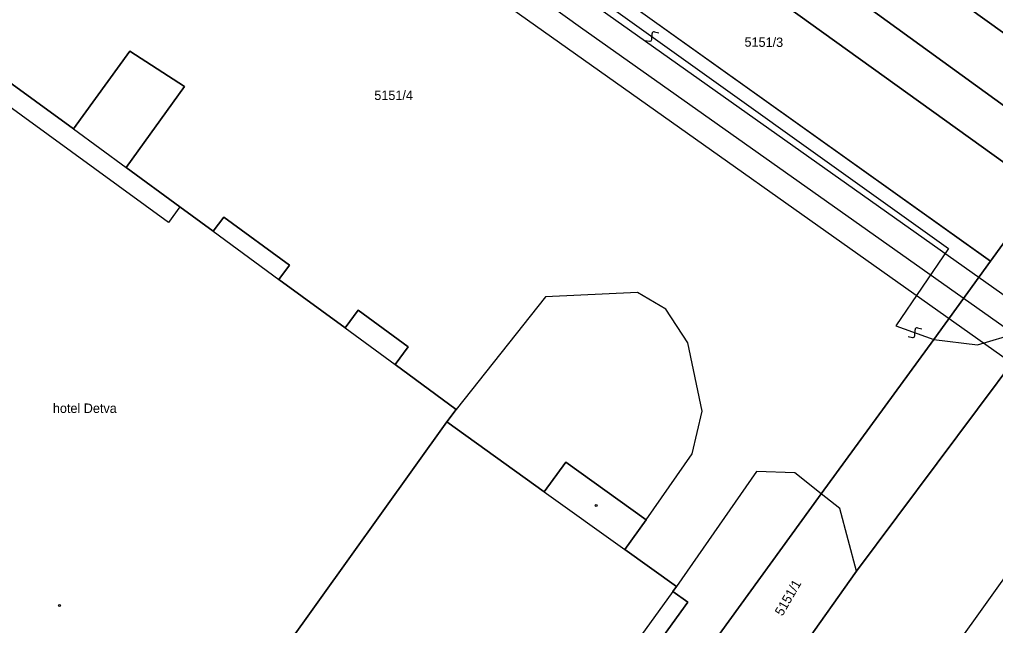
# Model space of a CAD drawing. Extents: x -400488 to -400124, y -1251493 to -1251223.
# Drawn here: x -400364.05 to -400314.45, y -1251437 to -1251406.21 of the extents above; entities that cross this region are included whole.
import ezdxf

# ---------------------------------------------------------------- set-up
doc = ezdxf.new("R2010")
doc.units = 0
doc.layers.add('Level 63', color=7, linetype='Continuous')

msp = doc.modelspace()

# ---------------------------------------------------------------- linework, layer by layer
at = {"layer": 'Level 63'}
for p, q in [((-400343.89, -1251392), (-400312.09, -1251414.87)), ((-400312.09, -1251414.87), (-400343.89, -1251392)), ((-400314.7, -1251418.49), (-400346.59, -1251395.74)), ((-400346.59, -1251395.74), (-400314.7, -1251418.49)), ((-400346.99, -1251396.3), (-400316.83, -1251417.85)), ((-400346.99, -1251396.3), (-400316.83, -1251417.85)), ((-400341.41, -1251400.8), (-400300.81, -1251429.57)), ((-400300.27, -1251433.14), (-400345.06, -1251401.4)), ((-400343.23, -1251401.1), (-400335.53, -1251406.59)), ((-400311.14, -1251408.98), (-400321.44, -1251401.55)), ((-400321.44, -1251401.55), (-400311.14, -1251408.98)), ((-400323.17, -1251403.95), (-400310.73, -1251412.98)), ((-400310.73, -1251412.98), (-400323.17, -1251403.95)), ((-400335.53, -1251406.59), (-400300.54, -1251431.36)), ((-400331.916, -1251407.222), (-400331.904, -1251406.928)), ((-400331.783, -1251406.834), (-400331.565, -1251406.882)), ((-400332.255, -1251407.268), (-400332.037, -1251407.316)), ((-400366.76, -1251407.8), (-400361.31, -1251411.77)), ((-400361.31, -1251411.77), (-400366.76, -1251407.8)), ((-400361.31, -1251411.77), (-400358.44, -1251407.82)), ((-400358.44, -1251407.82), (-400361.31, -1251411.77)), ((-400358.44, -1251407.82), (-400355.66, -1251409.61)), ((-400355.66, -1251409.61), (-400358.44, -1251407.82)), ((-400356.48, -1251416.53), (-400367.35, -1251408.62)), ((-400355.66, -1251409.61), (-400358.63, -1251413.73)), ((-400358.63, -1251413.73), (-400355.66, -1251409.61)), ((-400361.31, -1251411.77), (-400358.63, -1251413.73)), ((-400358.63, -1251413.73), (-400355.89, -1251415.73)), ((-400355.89, -1251415.73), (-400358.63, -1251413.73)), ((-400312.09, -1251414.87), (-400314.7, -1251418.49)), ((-400314.7, -1251418.49), (-400312.09, -1251414.87)), ((-400355.89, -1251415.73), (-400356.48, -1251416.53)), ((-400355.89, -1251415.73), (-400354.2, -1251416.97)), ((-400354.2, -1251416.97), (-400355.89, -1251415.73)), ((-400354.2, -1251416.97), (-400353.67, -1251416.25)), ((-400353.67, -1251416.25), (-400354.2, -1251416.97)), ((-400353.67, -1251416.25), (-400350.33, -1251418.69)), ((-400350.33, -1251418.69), (-400353.67, -1251416.25)), ((-400354.2, -1251416.97), (-400350.86, -1251419.42)), ((-400354.2, -1251416.97), (-400350.86, -1251419.42)), ((-400316.83, -1251417.85), (-400319.51, -1251421.77)), ((-400316.83, -1251417.85), (-400319.51, -1251421.77)), ((-400350.33, -1251418.69), (-400350.86, -1251419.42)), ((-400350.86, -1251419.42), (-400350.33, -1251418.69)), ((-400317.58, -1251422.47), (-400314.7, -1251418.49)), ((-400314.7, -1251418.49), (-400317.58, -1251422.47)), ((-400350.86, -1251419.42), (-400347.5, -1251421.88)), ((-400347.5, -1251421.88), (-400350.86, -1251419.42)), ((-400337.31, -1251420.3), (-400341.86, -1251426.02)), ((-400337.31, -1251420.3), (-400341.86, -1251426.02)), ((-400332.64, -1251420.08), (-400337.31, -1251420.3)), ((-400332.64, -1251420.08), (-400337.31, -1251420.3)), ((-400331.2, -1251420.92), (-400332.64, -1251420.08)), ((-400331.2, -1251420.92), (-400332.64, -1251420.08)), ((-400347.5, -1251421.88), (-400346.84, -1251420.98)), ((-400346.84, -1251420.98), (-400347.5, -1251421.88)), ((-400346.84, -1251420.98), (-400344.3, -1251422.84)), ((-400344.3, -1251422.84), (-400346.84, -1251420.98)), ((-400330.09, -1251422.64), (-400331.2, -1251420.92)), ((-400330.09, -1251422.64), (-400331.2, -1251420.92)), ((-400347.5, -1251421.88), (-400344.96, -1251423.74)), ((-400321.51, -1251434.24), (-400312.23, -1251421.8)), ((-400312.23, -1251421.8), (-400321.51, -1251434.24)), ((-400319.51, -1251421.77), (-400317.58, -1251422.47)), ((-400319.51, -1251421.77), (-400317.58, -1251422.47)), ((-400318.418, -1251421.879), (-400318.2, -1251421.927)), ((-400315.36, -1251422.74), (-400312.23, -1251421.8)), ((-400318.89, -1251422.313), (-400318.672, -1251422.361)), ((-400318.551, -1251422.267), (-400318.539, -1251421.973)), ((-400344.3, -1251422.84), (-400344.96, -1251423.74)), ((-400344.96, -1251423.74), (-400344.3, -1251422.84)), ((-400329.36, -1251426.11), (-400330.09, -1251422.64)), ((-400329.36, -1251426.11), (-400330.09, -1251422.64)), ((-400323.3, -1251430.31), (-400317.58, -1251422.47)), ((-400317.58, -1251422.47), (-400323.3, -1251430.31)), ((-400317.58, -1251422.47), (-400315.36, -1251422.74)), ((-400344.96, -1251423.74), (-400341.86, -1251426.02)), ((-400341.86, -1251426.02), (-400344.96, -1251423.74)), ((-400341.86, -1251426.02), (-400342.33, -1251426.66)), ((-400342.33, -1251426.66), (-400341.86, -1251426.02)), ((-400329.86, -1251428.28), (-400329.36, -1251426.11)), ((-400329.86, -1251428.28), (-400329.36, -1251426.11)), ((-400350.86, -1251438.57), (-400342.33, -1251426.66)), ((-400342.33, -1251426.66), (-400350.86, -1251438.57)), ((-400342.33, -1251426.66), (-400337.38, -1251430.21)), ((-400337.38, -1251430.21), (-400342.33, -1251426.66)), ((-400332.2, -1251431.63), (-400329.86, -1251428.28)), ((-400332.2, -1251431.63), (-400329.86, -1251428.28)), ((-400337.38, -1251430.21), (-400336.29, -1251428.7)), ((-400336.29, -1251428.7), (-400337.38, -1251430.21)), ((-400336.29, -1251428.7), (-400332.2, -1251431.63)), ((-400332.2, -1251431.63), (-400336.29, -1251428.7)), ((-400326.59, -1251429.17), (-400330.66, -1251435.02)), ((-400326.59, -1251429.17), (-400330.66, -1251435.02)), ((-400324.65, -1251429.24), (-400326.59, -1251429.17)), ((-400324.65, -1251429.24), (-400326.59, -1251429.17)), ((-400323.3, -1251430.31), (-400324.65, -1251429.24)), ((-400345.99, -1251461.49), (-400323.3, -1251430.31)), ((-400323.3, -1251430.31), (-400345.99, -1251461.49)), ((-400337.38, -1251430.21), (-400333.28, -1251433.14)), ((-400322.36, -1251431.06), (-400323.3, -1251430.31)), ((-400321.51, -1251434.24), (-400322.36, -1251431.06)), ((-400332.2, -1251431.63), (-400333.28, -1251433.14)), ((-400333.28, -1251433.14), (-400332.2, -1251431.63)), ((-400333.28, -1251433.14), (-400330.66, -1251435.02)), ((-400330.66, -1251435.02), (-400333.28, -1251433.14)), ((-400312.95, -1251433.09), (-400317.46, -1251439.39)), ((-400342.61, -1251463.85), (-400321.51, -1251434.24)), ((-400321.51, -1251434.24), (-400342.61, -1251463.85)), ((-400330.84, -1251435.27), (-400347.7, -1251458.61)), ((-400330.66, -1251435.02), (-400330.84, -1251435.27)), ((-400330.84, -1251435.27), (-400330.66, -1251435.02)), ((-400330.84, -1251435.27), (-400330.08, -1251435.81)), ((-400330.08, -1251435.81), (-400330.84, -1251435.27)), ((-400330.08, -1251435.81), (-400346.94, -1251459.15)), ((-400346.94, -1251459.15), (-400330.08, -1251435.81))]:
    msp.add_line(p, q, dxfattribs=at)
for centre in [(-400334.74, -1251430.906), (-400362.01, -1251435.986)]:
    msp.add_circle(centre, 0.054, dxfattribs=at)
for centre, start, end in [((-400331.804, -1251406.932), 77.7527, 177.7631), ((-400332.016, -1251407.218), 257.753, 357.7631), ((-400318.439, -1251421.977), 77.7527, 177.7631), ((-400318.651, -1251422.263), 257.753, 357.7631)]:
    msp.add_arc(centre, 0.1, start, end, dxfattribs=at)

# ---------------------------------------------------------------- texts
for s, rotation, p in [('5151/3', 359.44, (-400327.205, -1251407.59)), ('5151/1', 59.97, (-400325.279, -1251436.554))]:
    msp.add_text(s, height=0.48, rotation=rotation, dxfattribs=at).set_placement(p)
for s, p in [('5151/4', (-400346.016, -1251410.3)), ('hotel Detva', (-400362.35, -1251426.2))]:
    msp.add_text(s, height=0.48, dxfattribs=at).set_placement(p)

doc.saveas('drawing.dxf')
